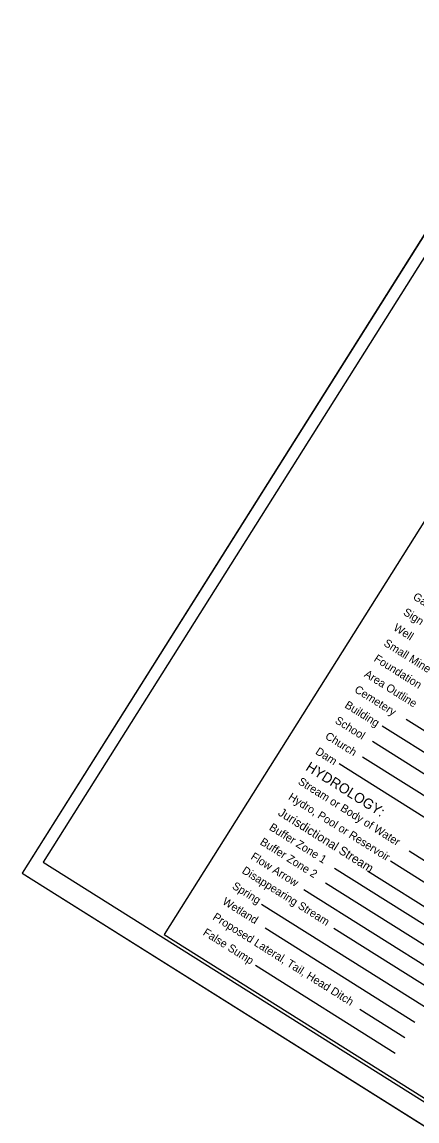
# Model space of a CAD drawing. Extents: x 2337092 to 2349158, y 800756 to 811724.
# Drawn here: x 2337092 to 2339681, y 804511 to 811724 of the extents above; entities that cross this region are included whole.
import ezdxf

# ---------------------------------------------------------------- set-up
doc = ezdxf.new("R2010")
doc.units = 0
for name, color, linetype in [('Sheet Cutting Line CELL', 7, 'Continuous'), ('Sheet Plot Border Inside CELL', 7, 'Continuous'), ('Sheet Plot Border Outside CELL', 7, 'Continuous'), ('Sheet Symbology CELL', 7, 'Continuous')]:
    doc.layers.add(name, color=color, linetype=linetype)

msp = doc.modelspace()

# ---------------------------------------------------------------- linework, layer by layer
at = {"layer": 'Sheet Cutting Line CELL'}
for p, q in [((2340607.3, 811723.5), (2337091.6, 806137.8)), ((2337091.6, 806137.8), (2345642.8, 800755.6))]:
    msp.add_line(p, q, dxfattribs=at)
at = {"layer": 'Sheet Plot Border Inside CELL'}
msp.add_lwpolyline([(2337229.4, 806210.3), (2345691.7, 800884), (2349063.9, 806241.7), (2340601.5, 811568)], close=True, dxfattribs=at)
at = {"layer": 'Sheet Plot Border Outside CELL'}
msp.add_lwpolyline([(2337091.6, 806137.8), (2345642.8, 800755.6), (2349158.5, 806341.3), (2340607.3, 811723.5)], close=True, dxfattribs=at)
at = {"layer": 'Sheet Symbology CELL'}
for p, q in [((2340571.3, 806540), (2339609.4, 807145.4)), ((2340507.4, 806438.5), (2339452.6, 807102.3)), ((2340443.4, 806336.9), (2339388.7, 807000.8)), ((2340379.5, 806235.4), (2339324.8, 806899.2)), ((2340315.6, 806133.8), (2339170.9, 806854.3)), ((2340161.7, 805945.7), (2339628.6, 806281.3)), ((2340097.8, 805844.1), (2339506.8, 806216.1)), ((2339972.5, 805645), (2339141, 806168.4)), ((2340025.6, 805729.4), (2339357.3, 806150)), ((2339912.2, 805549.2), (2339080.7, 806072.5)), ((2339851.9, 805453.3), (2338938.7, 806028.1)), ((2339730.1, 805259.8), (2338661.3, 805932.5)), ((2339666.1, 805158.2), (2338685, 805775.7)), ((2339794, 805361.3), (2339136.3, 805775.3)), ((2339538.3, 804955.1), (2338622.9, 805531.3)), ((2339602.2, 805056.7), (2339306.8, 805242.6))]:
    msp.add_line(p, q, dxfattribs=at)
msp.add_lwpolyline([(2348992.3, 806268.7), (2341375.4, 811062.8), (2338022.8, 805736.2), (2345639.6, 800942.1)], close=True, dxfattribs=at)

# ---------------------------------------------------------------- texts
for s, height, p in [('Gas Pump Vent or U/G Tank Cap', 52.5, (2339649.7, 807938.7)), ('Sign', 52.5, (2339585.9, 807837.2)), ('Well', 52.5, (2339522, 807735.6)), ('Small Mine', 52.5, (2339458, 807634)), ('Foundation', 52.5, (2339394.1, 807532.4)), ('Area Outline', 52.5, (2339330.2, 807430.9)), ('Cemetery', 52.5, (2339266.3, 807329.4)), ('Building', 52.5, (2339202.4, 807227.8)), ('School', 52.5, (2339138.4, 807126.3)), ('Church', 52.5, (2339074, 807023.7)), ('Dam', 52.5, (2339010.6, 806923.2)), ('HYDROLOGY:', 66, (2338946, 806817.4)), ('Stream or Body of Water', 52.5, (2338896.5, 806726)), ('Hydro, Pool or Reservoir', 52.5, (2338832.6, 806624.4)), ('Jurisdictional Stream', 57.876, (2338765.3, 806521.2)), ('Buffer Zone 1', 52.5, (2338707.3, 806425.3)), ('Buffer Zone 2', 52.5, (2338647, 806329.5)), ('Flow Arrow', 52.5, (2338586.7, 806233.6)), ('Disappearing Stream', 52.5, (2338528.8, 806141.6)), ('Spring', 52.5, (2338464.8, 806040.1)), ('Wetland', 52.5, (2338400.9, 805938.5)), ('Proposed Lateral, Tail, Head Ditch', 52.5, (2338337, 805837)), ('False Sump', 52.5, (2338273.1, 805735.4))]:
    msp.add_text(s, height=height, rotation=327.81344, dxfattribs=at).set_placement(p)

doc.saveas('drawing.dxf')
